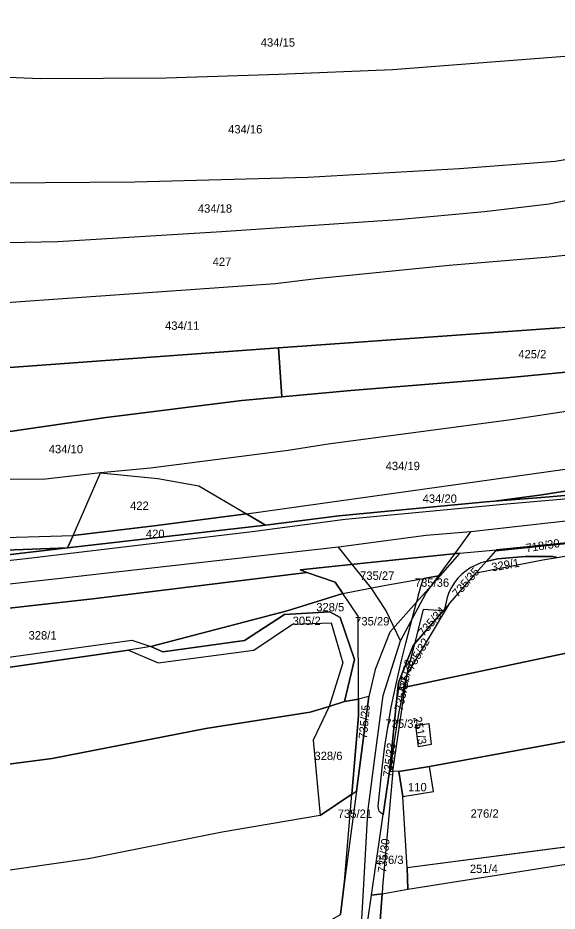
# Model space of a CAD drawing. Extents: x -629983 to -626385, y -1072828 to -1067897.
# Drawn here: x -628103.8 to -627910.7, y -1070963.6 to -1070643.4 of the extents above; entities that cross this region are included whole.
import ezdxf

# ---------------------------------------------------------------- set-up
doc = ezdxf.new("R2010")
doc.units = 0
for name, color, linetype in [('Parcela nároku', 7, 'Continuous'), ('Parcelní číslo', 7, 'Continuous'), ('Plocha PÚ', 7, 'Continuous'), ('silnice III třídy', 7, 'Continuous'), ('Silnice ŘSD', 7, 'Continuous'), ('Vnitřní obvod_šetřený', 7, 'Continuous')]:
    doc.layers.add(name, color=color, linetype=linetype)

msp = doc.modelspace()

# ---------------------------------------------------------------- linework, layer by layer
at = {"layer": 'Parcela nároku'}
for points in [[(-627903.25, -1070656.94), (-627969.61, -1070662.08), (-628010.4, -1070663.68), (-628050.69, -1070664.96), (-628095.77, -1070665.28), (-628130.82, -1070663.87), (-628192.91, -1070658.82), (-628232.19, -1070654.23), (-628265.99, -1070648.94), (-628263.64, -1070635.31), (-628259.61, -1070613.49), (-628222.19, -1070619.55), (-628170.37, -1070625.67), (-628130.69, -1070628.69), (-628086.68, -1070632.01), (-628060.6, -1070633.22), (-628020.49, -1070633.87), (-627969.04, -1070632.64), (-627947.86, -1070631.28), (-627921.14, -1070630.03), (-627870.01, -1070625.59)], [(-628806.74, -1070625.37), (-628693.42, -1070673.79), (-628643.05, -1070694.92), (-628550.51, -1070733.05), (-628487.8, -1070759.97), (-628390.08, -1070801.2), (-628299.13, -1070839.37), (-628282.87, -1070845.37), (-628222.34, -1070857.83), (-628221.85, -1070854.1), (-628194.61, -1070856.11), (-628176.53, -1070856.34), (-628175.29, -1070861.2), (-628171.38, -1070861.19), (-628123.2, -1070856.79), (-628077, -1070851.61), (-628000.36, -1070842.17), (-628002.78, -1070841.25), (-627960.57, -1070836.87), (-627945.52, -1070835.28), (-627932.44, -1070834.08), (-627845.93, -1070825.43)], [(-627903.25, -1070656.94), (-627969.61, -1070662.08), (-628010.4, -1070663.68), (-628050.69, -1070664.96), (-628095.77, -1070665.28), (-628130.82, -1070663.87), (-628192.91, -1070658.82), (-628232.19, -1070654.23), (-628265.99, -1070648.94), (-628270.74, -1070676.48), (-628273.28, -1070689.52), (-628252.05, -1070692.84), (-628196.68, -1070700.32), (-628169.65, -1070702.28), (-628128.71, -1070703.03), (-628110.17, -1070702.51), (-628061.9, -1070702.16), (-628000.02, -1070700.46), (-627945.67, -1070697.4), (-627911.39, -1070694.75), (-627878.35, -1070689.15)], [(-627880.72, -1070703.61), (-627913.59, -1070710.23), (-627936.72, -1070712.94), (-627967.91, -1070715.76), (-628030.92, -1070720.12), (-628089.53, -1070723.69), (-628119.2, -1070724.29), (-628143.14, -1070723.63), (-628169.3, -1070721.91), (-628208.02, -1070718.77), (-628244.23, -1070714.64), (-628277.25, -1070710.18), (-628276.73, -1070707.23), (-628273.28, -1070689.52), (-628252.05, -1070692.84), (-628196.68, -1070700.32), (-628169.65, -1070702.28), (-628128.71, -1070703.03), (-628110.17, -1070702.51), (-628061.9, -1070702.16), (-628000.02, -1070700.46), (-627945.67, -1070697.4), (-627911.39, -1070694.75), (-627878.35, -1070689.15)], [(-627910.01, -1070754.54), (-627980.13, -1070759.5), (-628010.48, -1070761.71), (-628106.74, -1070768.7), (-628139.79, -1070769.1), (-628169.73, -1070767.9), (-628184.29, -1070766.78), (-628241.28, -1070760.05), (-628273.61, -1070755.97), (-628285.01, -1070754.12), (-628280.94, -1070731.09), (-628263.51, -1070733.9), (-628210.4, -1070740.59), (-628200.21, -1070741.84), (-628160.37, -1070744.83), (-628148.47, -1070745.57), (-628116.56, -1070746.01), (-628089.45, -1070744.15), (-628011.54, -1070738.64), (-627997, -1070736.78), (-627949.38, -1070732.03), (-627913.55, -1070729.01), (-627881.94, -1070725.77)], [(-627886.24, -1070814.04), (-627928.69, -1070817.68), (-627986.6, -1070823.2), (-628019.88, -1070827.58), (-628101.01, -1070837.33), (-628160.56, -1070843.84), (-628166.52, -1070844.44), (-628180.6, -1070843.91), (-628197.6, -1070844.22), (-628212.49, -1070844.5), (-628228.13, -1070842.24), (-628240.58, -1070839.85), (-628257.57, -1070836.59), (-628279.58, -1070833.2), (-628327.59, -1070812.45), (-628429.24, -1070769.05)], [(-628107.59, -1070791.76), (-628072.18, -1070786.65), (-628023.62, -1070780.61), (-628009.29, -1070779.27), (-627984.57, -1070776.96), (-627928.72, -1070772.38), (-627893.78, -1070769.03)], [(-627891.66, -1070782.13), (-627927.13, -1070787.47), (-627992.73, -1070796.23), (-628007.05, -1070798.52), (-628056.38, -1070804.76), (-628074.3, -1070806.42), (-628093.93, -1070808.73), (-628119.22, -1070809.04)], [(-627979.86, -1070976.03), (-627977.2, -1070957.89), (-627972.97, -1070928.99), (-627973.77, -1070928.47), (-627974.39, -1070927.69), (-627974.71, -1070926.75), (-627974.74, -1070925.98), (-627973.36, -1070912.28), (-627972.37, -1070904.45), (-627970.09, -1070890.48), (-627968.28, -1070881.6), (-627966.43, -1070873.77), (-627964.91, -1070867.58), (-627963.16, -1070861.05), (-627961.05, -1070852.81), (-627970.65, -1070863.53), (-627975.92, -1070876.93), (-627978.15, -1070886.67), (-627982.59, -1070920.56), (-627986.83, -1070952.94), (-627988.33, -1070964.81)]]:
    msp.add_lwpolyline(points, dxfattribs=at)
for points in [[(-628089.53, -1070723.69), (-628119.2, -1070724.29), (-628143.14, -1070723.63), (-628169.3, -1070721.91), (-628208.02, -1070718.77), (-628210.4, -1070740.59), (-628200.21, -1070741.84), (-628160.37, -1070744.83), (-628148.47, -1070745.57), (-628116.56, -1070746.01), (-628089.45, -1070744.15), (-628011.54, -1070738.64), (-627997, -1070736.78), (-627949.38, -1070732.03), (-627913.55, -1070729.01), (-627881.94, -1070725.77), (-627827.95, -1070719.34), (-627825.9, -1070701.23), (-627853.73, -1070701.79), (-627880.72, -1070703.61), (-627913.59, -1070710.23), (-627936.72, -1070712.94), (-627967.91, -1070715.76), (-628030.92, -1070720.12)], [(-628010.48, -1070761.71), (-627980.13, -1070759.5), (-627910.01, -1070754.54), (-627876.95, -1070750.54), (-627830.99, -1070746.2), (-627833.01, -1070764.02), (-627893.78, -1070769.03), (-627928.72, -1070772.38), (-627984.57, -1070776.96), (-628009.29, -1070779.27)], [(-628010.48, -1070761.71), (-628009.29, -1070779.27), (-628023.62, -1070780.61), (-628072.18, -1070786.65), (-628107.59, -1070791.76), (-628116.86, -1070792.47), (-628169.95, -1070791.05), (-628211.46, -1070788.71), (-628241.06, -1070785.3), (-628278.54, -1070779.88), (-628289.22, -1070777.96), (-628285.01, -1070754.12), (-628273.61, -1070755.97), (-628241.28, -1070760.05), (-628184.29, -1070766.78), (-628169.73, -1070767.9), (-628139.79, -1070769.1), (-628106.74, -1070768.7)], [(-627927.13, -1070787.47), (-627992.73, -1070796.23), (-628007.05, -1070798.52), (-628056.38, -1070804.76), (-628074.3, -1070806.42), (-628053.65, -1070808.47), (-628039.03, -1070811.11), (-628022, -1070821.16), (-627888.28, -1070802.37), (-627891.66, -1070782.13)], [(-628247.27, -1070799.8), (-628259.3, -1070798.44), (-628291.95, -1070792.96), (-628296.36, -1070816.35), (-628247.12, -1070822.81), (-628216.56, -1070827.1), (-628187.75, -1070829.4), (-628149.38, -1070830.85), (-628083.99, -1070828.93), (-628074.3, -1070806.42), (-628093.93, -1070808.73), (-628119.22, -1070809.04), (-628148.65, -1070808.59), (-628185.16, -1070807.29), (-628203.61, -1070804.75), (-628226.8, -1070802.73)], [(-627888.28, -1070802.37), (-627887.07, -1070809.82), (-627909.33, -1070813.32), (-627916.13, -1070814.39), (-627933.12, -1070816.63), (-627936.08, -1070816.85), (-627988.85, -1070821.87), (-628015.19, -1070825.26), (-628022, -1070821.16)], [(-627909.33, -1070813.32), (-627881.43, -1070809.91), (-627859.39, -1070808.23), (-627831.35, -1070805.05), (-627831.35, -1070808.54), (-627832.77, -1070808.64), (-627880.7, -1070812.13), (-627886.52, -1070812.71), (-627913.43, -1070815.14), (-627933.12, -1070816.63), (-627916.13, -1070814.39)], [(-628053.65, -1070808.47), (-628039.03, -1070811.11), (-628022, -1070821.16), (-628055.08, -1070825.51), (-628083.99, -1070828.93), (-628074.3, -1070806.42)], [(-627886.52, -1070812.71), (-627886.24, -1070814.04), (-627928.69, -1070817.68), (-627986.6, -1070823.2), (-628019.88, -1070827.58), (-628101.01, -1070837.33), (-628160.56, -1070843.84), (-628166.52, -1070844.44), (-628180.6, -1070843.91), (-628165.45, -1070843.15), (-628157.61, -1070841.67), (-628086.12, -1070833.36), (-628015.19, -1070825.26), (-627988.85, -1070821.87), (-627936.08, -1070816.85), (-627933.12, -1070816.63), (-627913.43, -1070815.14)], [(-628247.12, -1070822.81), (-628216.56, -1070827.1), (-628187.75, -1070829.4), (-628149.38, -1070830.85), (-628083.99, -1070828.93), (-628086.12, -1070833.36), (-628117.9, -1070834.54), (-628138.98, -1070838.36), (-628147.23, -1070839.37), (-628156.65, -1070840.55), (-628173.41, -1070839.76), (-628175.41, -1070841.4), (-628188.29, -1070841.57), (-628193.58, -1070841.42), (-628203.49, -1070842.04), (-628212.49, -1070841.12), (-628246.75, -1070836.76), (-628265.95, -1070833.25), (-628287.56, -1070827.16), (-628297.64, -1070823.15), (-628296.36, -1070816.35)], [(-628022, -1070821.16), (-628015.19, -1070825.26), (-628086.12, -1070833.36), (-628083.99, -1070828.93), (-628055.08, -1070825.51)], [(-627801.49, -1070822.34), (-627781.59, -1070821.17), (-627788.59, -1070852.77), (-627795.23, -1070852.8), (-627829.54, -1070855.03), (-627855.66, -1070858.18), (-627871.1, -1070863.63), (-627903.55, -1070870.3), (-627965.1, -1070883.25), (-627964.44, -1070878.78), (-627949.1, -1070853.24), (-627939.64, -1070842.36), (-627915.75, -1070837.66), (-627910.72, -1070836.78), (-627868.6, -1070829.4), (-627844.7, -1070826.54), (-627829.74, -1070827.42), (-627824.59, -1070826.82), (-627818.12, -1070823.77)], [(-627845.93, -1070825.43), (-627932.79, -1070834.48), (-627936.07, -1070838.25), (-627932.01, -1070837.3), (-627922.17, -1070836.42), (-627912.26, -1070836.43), (-627910.72, -1070836.78), (-627868.6, -1070829.4)], [(-627845.93, -1070825.43), (-627932.44, -1070834.08), (-627932.79, -1070834.48)], [(-628175.41, -1070841.4), (-628173.41, -1070839.76), (-628156.65, -1070840.55), (-628147.23, -1070839.37), (-628138.98, -1070838.36), (-628117.9, -1070834.54), (-628086.12, -1070833.36), (-628157.61, -1070841.67)], [(-627952.49, -1070843.24), (-627946.36, -1070836.3), (-627945.52, -1070835.28), (-627932.44, -1070834.08), (-627932.79, -1070834.48), (-627936.07, -1070838.25), (-627938, -1070838.79), (-627939.86, -1070839.52), (-627941.63, -1070840.45), (-627943.3, -1070841.55), (-627944.84, -1070842.83), (-627946.24, -1070844.26), (-627947.48, -1070845.83), (-627948.55, -1070847.53), (-627949.43, -1070849.32), (-627950.12, -1070851.21), (-627950.73, -1070853.83), (-627950.98, -1070855.39), (-627951.5, -1070855.98), (-627958.64, -1070855.46), (-627961.82, -1070867.78), (-627962.17, -1070868.18), (-627967.53, -1070881.64), (-627967.75, -1070883.83), (-627970.71, -1070913.56), (-627972.97, -1070928.99), (-627973.77, -1070928.47), (-627974.39, -1070927.69), (-627974.71, -1070926.75), (-627974.74, -1070925.98), (-627973.36, -1070912.28), (-627972.37, -1070904.45), (-627970.09, -1070890.48), (-627968.28, -1070881.6), (-627966.43, -1070873.77), (-627964.91, -1070867.58), (-627963.16, -1070861.05), (-627961.05, -1070852.81)], [(-627960.57, -1070836.87), (-628002.78, -1070841.25), (-628000.36, -1070842.17), (-627990.17, -1070845.69), (-627987.49, -1070849.7), (-627973.33, -1070846.97), (-627958.49, -1070844.31), (-627952.49, -1070843.24), (-627946.36, -1070836.3), (-627945.52, -1070835.28)], [(-627912.26, -1070836.43), (-627922.17, -1070836.42), (-627932.01, -1070837.3), (-627936.07, -1070838.25), (-627939.64, -1070842.36), (-627915.75, -1070837.66), (-627910.72, -1070836.78)], [(-627949.43, -1070849.32), (-627950.12, -1070851.21), (-627950.73, -1070853.83), (-627950.98, -1070855.39), (-627949.1, -1070853.24), (-627939.64, -1070842.36), (-627936.07, -1070838.25), (-627938, -1070838.79), (-627939.86, -1070839.52), (-627941.63, -1070840.45), (-627943.3, -1070841.55), (-627944.84, -1070842.83), (-627946.24, -1070844.26), (-627947.48, -1070845.83), (-627948.55, -1070847.53)], [(-628171.38, -1070861.19), (-628175.29, -1070861.2), (-628182.16, -1070861.21), (-628215.75, -1070880.91), (-628190.3, -1070881.53), (-628166.04, -1070880.67), (-628063.03, -1070866.47), (-628056.23, -1070868.75), (-628007.41, -1070855.92), (-627987.49, -1070849.7), (-627990.17, -1070845.69), (-628000.36, -1070842.17), (-628077, -1070851.61), (-628123.2, -1070856.79)], [(-627973.33, -1070846.97), (-627958.49, -1070844.31), (-627958.89, -1070845.22), (-627959.63, -1070847.33), (-627960.54, -1070850.84), (-627961.05, -1070852.81), (-627970.65, -1070863.53), (-627975.92, -1070876.93), (-627978.15, -1070886.67), (-627981.83, -1070887.65), (-627982, -1070857.89), (-627987.49, -1070849.7)], [(-627960.54, -1070850.84), (-627961.05, -1070852.81), (-627952.49, -1070843.24), (-627958.49, -1070844.31), (-627958.89, -1070845.22), (-627959.63, -1070847.33)], [(-627987.49, -1070849.7), (-628007.41, -1070855.92), (-628056.23, -1070868.75), (-628051.9, -1070870.64), (-628022.68, -1070866.58), (-628008.33, -1070857.22), (-627992.15, -1070856.33), (-627988.38, -1070858.31), (-627983.25, -1070873.42), (-627986.88, -1070888.44), (-627981.83, -1070887.65), (-627982, -1070857.89)], [(-627969.54, -1070913.45), (-627965.1, -1070883.25), (-627903.55, -1070870.3), (-627871.1, -1070863.63), (-627855.66, -1070858.18), (-627829.54, -1070855.03), (-627795.23, -1070852.8), (-627788.59, -1070852.77), (-627793.29, -1070873.99), (-627796.08, -1070886.23), (-627856.91, -1070893.83), (-627904.38, -1070902.22), (-627956.41, -1070911.75), (-627967.36, -1070913.5)], [(-627951.5, -1070855.98), (-627961.82, -1070867.78), (-627964.27, -1070877.48), (-627965.59, -1070883.36), (-627965.1, -1070883.25), (-627964.44, -1070878.78), (-627949.1, -1070853.24), (-627950.98, -1070855.39)], [(-628056.23, -1070868.75), (-628064.22, -1070870.06), (-628053.62, -1070874.59), (-628019.31, -1070869.99), (-628005.42, -1070860.68), (-627991.64, -1070860.27), (-627987.41, -1070874.59), (-627992.36, -1070890.28), (-627986.88, -1070888.44), (-627983.25, -1070873.42), (-627988.38, -1070858.31), (-627992.15, -1070856.33), (-628008.33, -1070857.22), (-628022.68, -1070866.58), (-628051.9, -1070870.64)], [(-627951.5, -1070855.98), (-627958.64, -1070855.46), (-627961.82, -1070867.78)], [(-628005.42, -1070860.68), (-627991.64, -1070860.27), (-627987.41, -1070874.59), (-627992.36, -1070890.28), (-627999.17, -1070892.22), (-628036.55, -1070898.1), (-628091.52, -1070908.87), (-628135.68, -1070914.66), (-628171.14, -1070915.49), (-628186.02, -1070915.12), (-628227.81, -1070913.26), (-628252.66, -1070911.12), (-628263.14, -1070909.11), (-628221.13, -1070884.07), (-628168.4, -1070886.19), (-628139.07, -1070880.8), (-628064.22, -1070870.06), (-628053.62, -1070874.59), (-628019.31, -1070869.99)], [(-628166.04, -1070880.67), (-628063.03, -1070866.47), (-628056.23, -1070868.75), (-628064.22, -1070870.06), (-628139.07, -1070880.8), (-628168.4, -1070886.19), (-628221.13, -1070884.07), (-628215.75, -1070880.91), (-628190.3, -1070881.53)], [(-627967.53, -1070881.64), (-627962.17, -1070868.18), (-627961.82, -1070867.78), (-627964.27, -1070877.48), (-627965.59, -1070883.36), (-627967.75, -1070883.83)], [(-627970.71, -1070913.56), (-627967.75, -1070883.83), (-627965.59, -1070883.36), (-627966.79, -1070889.23), (-627967.35, -1070892.18), (-627967.88, -1070895.14), (-627968.85, -1070901.06), (-627969.69, -1070906.99), (-627970.48, -1070913.54)], [(-627965.59, -1070883.36), (-627966.79, -1070889.23), (-627967.35, -1070892.18), (-627967.88, -1070895.14), (-627968.85, -1070901.06), (-627969.69, -1070906.99), (-627970.48, -1070913.54), (-627969.54, -1070913.45), (-627965.1, -1070883.25)], [(-627986.88, -1070888.44), (-627992.36, -1070890.28), (-627998.03, -1070902.28), (-627995.58, -1070929.26), (-627984.18, -1070921.67), (-627981.8, -1070893.54), (-627981.83, -1070887.65)], [(-627978.15, -1070886.67), (-627981.83, -1070887.65), (-627981.8, -1070893.54), (-627984.18, -1070921.67), (-627982.59, -1070920.56)], [(-628227.81, -1070913.26), (-628186.02, -1070915.12), (-628171.14, -1070915.49), (-628135.68, -1070914.66), (-628091.52, -1070908.87), (-628036.55, -1070898.1), (-627999.17, -1070892.22), (-627992.36, -1070890.28), (-627998.03, -1070902.28), (-627995.58, -1070929.26), (-628030.61, -1070935.24), (-628078.59, -1070944.87), (-628135.03, -1070952.93), (-628198.8, -1070953.87), (-628250.8, -1070951.29), (-628298.12, -1070946.76), (-628311.98, -1070944.35), (-628300.59, -1070936.02), (-628263.14, -1070909.11), (-628252.66, -1070911.12)], [(-627956.68, -1070896.37), (-627955.79, -1070903.82), (-627960.3, -1070904.66), (-627961.25, -1070897.02)], [(-627955.79, -1070903.82), (-627960.3, -1070904.66), (-627961.25, -1070897.02), (-627956.68, -1070896.37)], [(-627904.38, -1070902.22), (-627901.16, -1070939.77), (-627964.42, -1070948.04), (-627965.93, -1070922.44), (-627954.97, -1070920.68), (-627956.41, -1070911.75)], [(-627954.97, -1070920.68), (-627956.41, -1070911.75), (-627967.36, -1070913.5), (-627965.93, -1070922.44)], [(-627977.2, -1070957.89), (-627972.97, -1070928.99), (-627970.71, -1070913.56), (-627970.48, -1070913.54), (-627969.54, -1070913.45), (-627973.19, -1070954.87), (-627973.38, -1070957.36)], [(-627967.36, -1070913.5), (-627969.54, -1070913.45), (-627973.19, -1070954.87), (-627973.38, -1070957.36), (-627964.22, -1070955.75), (-627964.42, -1070948.04), (-627965.93, -1070922.44)], [(-627986.83, -1070952.94), (-627984.18, -1070921.67), (-627982.59, -1070920.56)], [(-627864.34, -1070930.66), (-627792.28, -1070921.41), (-627763.16, -1070918.66), (-627764.01, -1070947.18), (-627768.7, -1070954.14), (-627774.12, -1070954.69), (-627825.12, -1070961.06), (-627854.63, -1070966.13), (-627874.47, -1070970.81), (-627897.8, -1070977.31), (-627975.92, -1070991.3), (-627973.38, -1070957.36), (-627964.22, -1070955.75), (-627900.65, -1070945.66), (-627896.65, -1070944.27)], [(-628331.46, -1070958.61), (-628354.57, -1070975.46), (-628250.75, -1070992.75), (-628210.59, -1070996.63), (-628170.63, -1070998.53), (-628137.42, -1070996.44), (-628108.15, -1070991.5), (-628036.8, -1070976.12), (-628000.12, -1070970.48), (-627993.94, -1070968.01), (-627988.33, -1070964.81), (-627986.83, -1070952.94), (-627984.18, -1070921.67), (-627995.58, -1070929.26), (-628030.61, -1070935.24), (-628078.59, -1070944.87), (-628135.03, -1070952.93), (-628198.8, -1070953.87), (-628250.8, -1070951.29), (-628298.12, -1070946.76), (-628311.98, -1070944.35)], [(-627901.16, -1070939.77), (-627964.42, -1070948.04), (-627964.22, -1070955.75), (-627900.65, -1070945.66)], [(-627981, -1070992.26), (-627979.86, -1070976.03), (-627977.2, -1070957.89), (-627973.38, -1070957.36), (-627975.92, -1070991.3)]]:
    msp.add_lwpolyline(points, close=True, dxfattribs=at)
at = {"layer": 'Plocha PÚ'}
msp.add_lwpolyline([(-627904.38, -1070902.22), (-627901.16, -1070939.77), (-627964.42, -1070948.04), (-627965.93, -1070922.44), (-627967.36, -1070913.5), (-627956.41, -1070911.75)], close=True, dxfattribs=at)
at = {"layer": 'silnice III třídy'}
for points in [[(-627982.94, -1071005.46), (-627980.45, -1070962.32), (-627979.85, -1070951.87), (-627978.48, -1070928.05), (-627975.81, -1070907.81), (-627972.97, -1070886.27), (-627966.83, -1070866.65), (-627957.77, -1070849.78), (-627951.22, -1070840.86), (-627945.03, -1070832.43), (-627941.61, -1070827.63)], [(-627966.83, -1070866.65), (-627972.02, -1070855.73), (-627977.34, -1070847.66), (-627982.9, -1070840.72), (-627989.02, -1070833.08)]]:
    msp.add_lwpolyline(points, dxfattribs=at)
at = {"layer": 'Silnice ŘSD'}
for p, q in [((-627957.65, -1070828.97), (-627989.02, -1070833.08)), ((-627989.02, -1070833.08), (-628068.67, -1070842.11)), ((-628087.5, -1070844.24), (-628119, -1070847.8)), ((-628068.67, -1070842.11), (-628087.5, -1070844.24))]:
    msp.add_line(p, q, dxfattribs=at)
msp.add_lwpolyline([(-627892.77, -1070822.13), (-627941.61, -1070827.63), (-627957.65, -1070828.97)], dxfattribs=at)
at = {"layer": 'Vnitřní obvod_šetřený'}
for p, q in [((-627956.41, -1070911.75), (-627904.38, -1070902.22)), ((-627967.36, -1070913.5), (-627956.41, -1070911.75)), ((-627965.93, -1070922.44), (-627967.36, -1070913.5)), ((-627964.42, -1070948.04), (-627965.93, -1070922.44)), ((-627901.16, -1070939.77), (-627964.42, -1070948.04))]:
    msp.add_line(p, q, dxfattribs=at)

# ---------------------------------------------------------------- texts
at = {"layer": 'Parcelní číslo'}
for s, p in [('434/15', (-628016.83, -1070653.72)), ('434/16', (-628028.53, -1070684.82)), ('434/18', (-628039.37, -1070713.24)), ('427', (-628034.08, -1070732.32)), ('434/11', (-628051.13, -1070755.21)), ('425/2', (-627924.59, -1070765.44)), ('434/10', (-628092.76, -1070799.46)), ('434/19', (-627972.11, -1070805.52)), ('434/20', (-627958.86, -1070817.23)), ('422', (-628063.66, -1070819.77)), ('420', (-628057.98, -1070829.83)), ('735/27', (-627981.26, -1070844.84)), ('735/36', (-627961.64, -1070847.33)), ('328/5', (-627996.96, -1070856.12)), ('305/2', (-628005.41, -1070861.03)), ('735/29', (-627983.03, -1070861.18)), ('328/1', (-628100.01, -1070866.22)), ('735/31', (-627972.18, -1070897.88)), ('328/6', (-627997.61, -1070909.43)), ('110', (-627964.1, -1070920.64)), ('735/21', (-627989.24, -1070930.17)), ('276/2', (-627941.68, -1070930.09)), ('276/3', (-627975.74, -1070946.68)), ('251/4', (-627941.95, -1070949.9))]:
    msp.add_text(s, height=3, dxfattribs=at).set_placement(p)
for s, rotation, p in [('718/30', 8.8418, (-627921.67, -1070834.97)), ('329/1', 9.9389, (-627933.91, -1070841.83)), ('735/35', 48.9677, (-627946.31, -1070851.3)), ('735/34', 48.9677, (-627958.48, -1070865.32)), ('735/32', 59.9212, (-627962.35, -1070877.47)), ('735/38', 77.3474, (-627964.85, -1070885.72)), ('735/37', 77.3474, (-627966.12, -1070891.94)), ('735/25', 84.7904, (-627978.82, -1070901.93)), ('251/3', 280.8641, (-627962.23, -1070894.21)), ('735/33', 82.794, (-627970.09, -1070915.62)), ('735/30', 83.6598, (-627971.99, -1070949.97))]:
    msp.add_text(s, height=3, rotation=rotation, dxfattribs=at).set_placement(p)

doc.saveas('drawing.dxf')
